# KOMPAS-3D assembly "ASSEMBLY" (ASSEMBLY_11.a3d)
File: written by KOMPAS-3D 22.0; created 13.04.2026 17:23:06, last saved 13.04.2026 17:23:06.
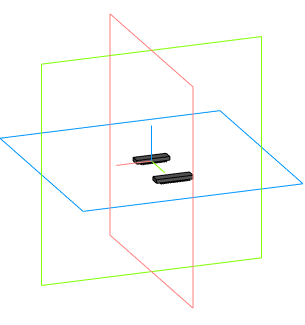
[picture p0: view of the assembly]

Document properties: Автор: Andrey; Полное имя файла: C:\Users\User1\Documents\ASSEMBLY_11.a3d

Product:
- Component [detail]: Body  | qty 1  | source file: Body_12.m3d
- Component [detail]: Pins  | qty 1  | source file: Pins.m3d
- Component [assembly]: ASSEMBLY  | qty 1  | source file: ASSEMBLY_13.a3d
- Part/product: ASSEMBLY

Referenced files in C:\Users\User1\Documents\: Body_12.m3d, Pins.m3d, ASSEMBLY_13.a3d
